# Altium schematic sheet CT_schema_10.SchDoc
size 147 x 119 mm
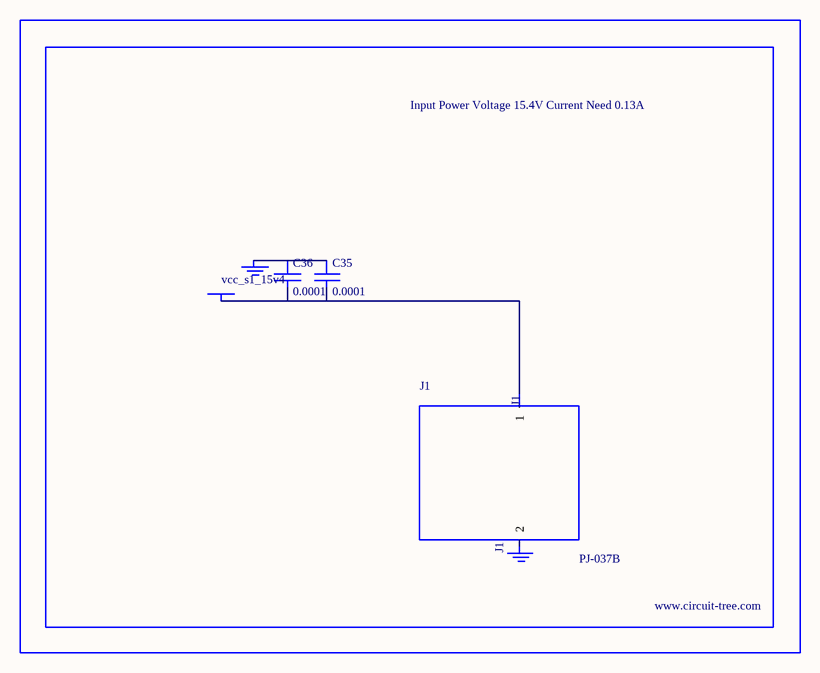
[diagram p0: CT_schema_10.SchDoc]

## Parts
BORDER9  (no value)
C35  0.0001  [EXV-9H]
C36  0.0001  [EXV-9H]
GND_INSTANCE_9_0  (no value)
GND_INSTANCE_9_1  (no value)
J1  PJ-037B  [PJ-037B_PACKAGE]
POWER_INSTANCE_9_0  vcc_s1_15v4

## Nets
NetC35_1: C35.1 C36.1 GND_INSTANCE_9_0.0(GND)
NetC35_2: C35.2 C36.2 J1.1 POWER_INSTANCE_9_0.0(PWR)

Not connected (* = marked no-connect by the designer): GND_INSTANCE_9_1 0(GND); J1 2

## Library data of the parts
BORDER9 = BORDER_PAGE9
C35 C36 = EDK107M035A9HAA
GND_INSTANCE_9_0 GND_INSTANCE_9_1 = GND
POWER_INSTANCE_9_0 = PWR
